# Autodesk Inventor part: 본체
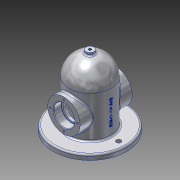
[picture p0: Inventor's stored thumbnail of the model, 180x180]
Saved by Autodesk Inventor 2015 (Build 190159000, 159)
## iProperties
Created: 2019-11
Part Number: 본체
Material: 알루미늄 6061
Document SubType Name: Modeling
Designer: Administrator
Density: 2.7 g/cm^3
Appearance: 알루미늄 - 평지
Mass: 1106.12 g
Surface Area: 883.263 cm^2
Volume: 409.676 cm^3
Author: Administrator
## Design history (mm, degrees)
sketch "스케치1"
  geometry: C1 r 70 at (0, 0); 1 further point
  constraints: 1 centre point, 1 coincident
  dimensions: "d0" = 140 diameter of C1
extrude "돌출1" new body sketch "스케치1" distance "d1" = 10; taper "d2" = 0 deg
sketch "스케치2"
  geometry: C1 r 40 at (0, 0); 1 further point
  constraints: 1 centre point, 1 coincident
  dimensions: "d3" = 80 diameter of C1
extrude "돌출2" join sketch "스케치2" distance "d4" = 80; taper "d5" = 0 deg
sketch "스케치3"
  geometry: L1 (90, -40)-(90, 40) reference; L2 (10, 40)-(10, -40) reference; L3 (90, 0)-(130, 0); L4 (90, 0)-(90, -40); A1 r 40 centre (90, 0) between (90, -40) and (130, 0); 1 further point
  constraints: 5 end point, 2 point on circle, 1 centre point, 1 coincident, 1 horizontal, 1 midpoint, 1 vertical
revolve "회전1" sketch "스케치3" stored, may be unused: angle "d7" = 90 deg
node "작업 평면1"
sketch "스케치4"
  geometry: C1 r 7.5 at (0, 0); 1 further point
  constraints: 1 centre point, 1 coincident
  dimensions: "d9" = 15 diameter of C1
extrude "돌출3" join sketch "스케치4" distance "d10" = 17; taper "d11" = 0 deg
sketch "스케치7"
  geometry: C1 r 31 at (0, 50); 1 further point
  constraints: 1 centre point, 1 vertical alignment
  dimensions: "d17" = 62 diameter of C1; "d18" = 50 distance of point (0, 0) C1.centre
extrude "돌출5" join sketch "스케치7" stored distance "d19" = 100; taper "d20" = 0 deg
sketch "스케치8"
  geometry: C1 r 30 at (0, 0); 1 further point
  constraints: 1 centre point, 1 coincident
  dimensions: "d21" = 60 diameter of C1
extrude "돌출6" cut sketch "스케치8" distance "d22" = 90; taper "d23" = 0 deg
sketch "스케치9"
  geometry: L1 (90, -30)-(90, 30) reference; L2 (90, 0)-(120, 0); L3 (90, 0)-(90, -30); A1 r 30 centre (90, 0) between (90, -30) and (120, 0); 1 further point
  constraints: 6 end point, 2 point on circle, 1 centre point, 1 collinear, 1 horizontal, 1 midpoint
revolve "회전3" sketch "스케치9" stored, may be unused: angle "d25" = 90 deg
sketch "스케치10"
  geometry: C1 r 31 at (0, 0) reference; C2 r 20 at (0, 0); 1 further point
  constraints: 1 centre point, 1 coincident
  dimensions: "d26" = 40 diameter of C2
extrude "돌출7" cut sketch "스케치10" distance "d27" = 15; taper "d28" = 0 deg
sketch "스케치11"
  geometry: C1 r 31 at (0, 0) reference; C2 r 20 at (0, 0); 1 further point
  constraints: 1 centre point, 1 coincident
  dimensions: "d29" = 40 diameter of C2
extrude "돌출8" cut sketch "스케치11" distance "d30" = 15; taper "d31" = 0 deg
sketch "스케치12"
  geometry: C1 r 20 at (0, 0) reference; C2 r 16.5 at (0, 0); 1 further point
  constraints: 1 centre point, 1 coincident
  dimensions: "d32" = 33 diameter of C2
extrude "돌출9" cut sketch "스케치12" distance "d33" = 111.25; taper "d34" = 0 deg
fillet "모깎기1" dims "d35" = 0.3
sketch "스케치13"
  geometry: C1 r 31 at (0, 0) reference; 2 further points
  constraints: 1 vertical alignment
  dimensions: "d36" = 26 distance of point (0, 26) C1.centre
hole "구멍1" sketch "스케치13" at (0, 26) diameter "d37" = 3.242; stored, may be unused: countersink angle "d41" = 90 deg, drill point angle "d43" = 118 deg; dims "d38" = 8, "d39" = 4, "d40" = 2, "d42" = 10
sketch "스케치14"
  geometry: C1 r 31 at (0, 0) reference; 2 further points
  constraints: 1 vertical alignment
  dimensions: "d47" = 26 distance of point (0, 26) C1.centre
hole "구멍2" sketch "스케치14" at (0, 26) diameter "d48" = 3.242; stored, may be unused: countersink angle "d52" = 90 deg, drill point angle "d54" = 118 deg; dims "d49" = 8, "d50" = 4, "d51" = 2, "d53" = 10
chamfer "모따기1" distance "d58" = 1; stored, may be unused: second distance "d59" = 2, angle "d60" = 45 deg
hole "구멍3" diameter "d63" = 5.188; stored, may be unused: countersink angle "d67" = 90 deg, drill point angle "d69" = 118 deg; dims "d61" = 10, "d62" = 10, "d64" = 90, "d65" = 4, "d66" = 2, "d68" = 93.75
fillet "모깎기2" dims "d70" = 3
sketch "스케치15"
  geometry: A1 r 55 centre (0, 0) between (55, 0) and (-55, 0); 1 further point
  constraints: 2 horizontal alignment, 2 point on circle, 1 centre point, 1 coincident
  dimensions: "d71" = 110 diameter of A1
hole "구멍4" sketch "스케치15" at (55, 0), (-55, 0) diameter "d72" = 9; stored, may be unused: countersink angle "d76" = 90 deg, drill point angle "d78" = 118 deg; dims "d73" = 90, "d74" = 4, "d75" = 2, "d77" = 10
node "작업 평면2"
sketch "스케치16"
  geometry: L1 (-10, 70)-(-10, -70) reference; 2 further points
  constraints: 1 horizontal alignment, 1 other
  dimensions: "d79" = 50 distance from line of point (40, 0) L1
feature "엠보싱1" sketch "스케치16" dims "d80" = 0.5, "d81" = 0
node "솔리드1"
pattern_circular "원형 패턴1" dims angle "d45" = 360 deg
pattern_circular "원형 패턴2" dims angle "d56" = 360 deg
node "투영된 루프1"
node "투영된 루프2"
node "투영된 루프3"
node "투영된 루프4"
other parameters: "d8" = 135
